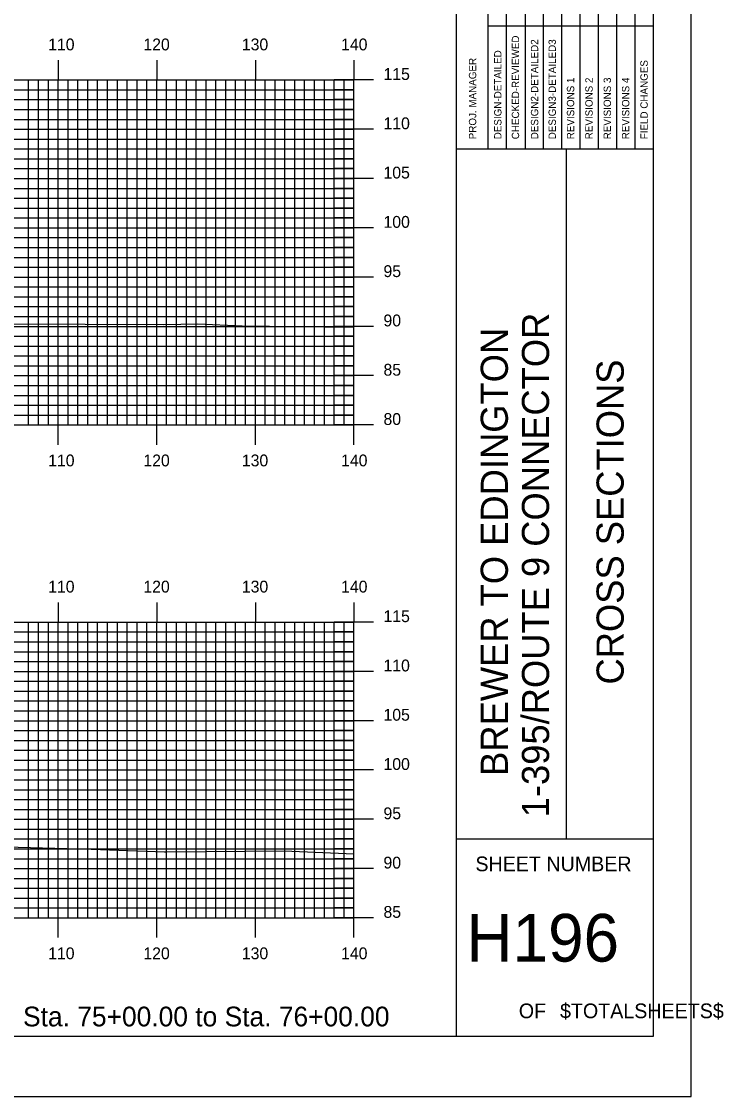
# Model space of a CAD drawing. Extents: x 1761397 to 1761741, y 442591 to 442811.
# Drawn here: x 1761669.5 to 1761740.7, y 442590.5 to 442699.6 of the extents above; entities that cross this region are included whole.
import ezdxf

# ---------------------------------------------------------------- set-up
doc = ezdxf.new("R2010")
doc.units = 0
for name, color, linetype in [('BORDER', 7, 'Continuous'), ('H_V ANNOTATION', 7, 'Continuous'), ('MAJOR', 7, 'Continuous'), ('MINOR', 7, 'Continuous'), ('PLOT BOUNDARY', 7, 'Continuous'), ('S_Roadway_Centerline', 7, 'Continuous')]:
    doc.layers.add(name, color=color, linetype=linetype)

msp = doc.modelspace()

# ---------------------------------------------------------------- linework, layer by layer
at = {"layer": 'BORDER'}
for p, q in [((1761713.64, 442596.67), (1761713.64, 442806.67)), ((1761713.64, 442686.67), (1761733.64, 442686.67)), ((1761724.82, 442616.67), (1761724.82, 442686.67)), ((1761713.64, 442616.67), (1761733.64, 442616.67))]:
    msp.add_line(p, q, dxfattribs=at)
msp.add_lwpolyline([(1761413.64, 442596.67), (1761733.64, 442596.67), (1761733.64, 442806.67), (1761413.64, 442806.67)], close=True, dxfattribs=at)
for points in [[(1761718.73, 442686.68), (1761718.73, 442721.67)], [(1761720.6, 442721.67), (1761720.6, 442686.68)], [(1761722.46, 442686.68), (1761722.46, 442721.67)], [(1761724.33, 442686.68), (1761724.33, 442721.67)], [(1761726.19, 442686.68), (1761726.19, 442721.67)], [(1761728.05, 442686.68), (1761728.05, 442721.67)], [(1761729.92, 442686.68), (1761729.92, 442721.67)], [(1761731.78, 442686.68), (1761731.78, 442721.67)], [(1761716.87, 442686.68), (1761716.87, 442720.26)], [(1761716.87, 442699.17), (1761733.64, 442699.17)]]:
    msp.add_lwpolyline(points, dxfattribs=at)
at = {"layer": 'MAJOR'}
for p, q in [((1761673.24, 442695.67), (1761673.24, 442693.67)), ((1761683.24, 442695.67), (1761683.24, 442693.67)), ((1761693.24, 442695.67), (1761693.24, 442693.67)), ((1761703.24, 442695.67), (1761703.24, 442693.67)), ((1761423.24, 442693.67), (1761703.24, 442693.67)), ((1761423.24, 442693.67), (1761703.24, 442693.67)), ((1761673.24, 442658.67), (1761673.24, 442693.67)), ((1761683.24, 442658.67), (1761683.24, 442693.67)), ((1761693.24, 442658.67), (1761693.24, 442693.67)), ((1761705.24, 442693.67), (1761701.24, 442693.67)), ((1761703.24, 442658.67), (1761703.24, 442693.67)), ((1761703.24, 442658.67), (1761703.24, 442693.67)), ((1761423.24, 442688.67), (1761703.24, 442688.67)), ((1761705.24, 442688.67), (1761701.24, 442688.67)), ((1761423.24, 442683.67), (1761703.24, 442683.67)), ((1761705.24, 442683.67), (1761701.24, 442683.67)), ((1761423.24, 442678.67), (1761703.24, 442678.67)), ((1761705.24, 442678.67), (1761701.24, 442678.67)), ((1761423.24, 442673.67), (1761703.24, 442673.67)), ((1761705.24, 442673.67), (1761701.24, 442673.67)), ((1761423.24, 442668.67), (1761703.24, 442668.67)), ((1761705.24, 442668.67), (1761701.24, 442668.67)), ((1761423.24, 442663.67), (1761703.24, 442663.67)), ((1761705.24, 442663.67), (1761701.24, 442663.67)), ((1761423.24, 442658.67), (1761703.24, 442658.67)), ((1761423.24, 442658.67), (1761703.24, 442658.67)), ((1761673.24, 442656.66), (1761673.24, 442658.67)), ((1761683.24, 442656.66), (1761683.24, 442658.67)), ((1761693.24, 442656.66), (1761693.24, 442658.67)), ((1761705.24, 442658.67), (1761701.24, 442658.67)), ((1761703.24, 442656.66), (1761703.24, 442658.67)), ((1761673.24, 442640.67), (1761673.24, 442638.67)), ((1761683.24, 442640.67), (1761683.24, 442638.67)), ((1761693.24, 442640.67), (1761693.24, 442638.67)), ((1761703.24, 442640.67), (1761703.24, 442638.67)), ((1761423.24, 442638.67), (1761703.24, 442638.67)), ((1761423.24, 442638.67), (1761703.24, 442638.67)), ((1761673.24, 442608.67), (1761673.24, 442638.67)), ((1761683.24, 442608.67), (1761683.24, 442638.67)), ((1761693.24, 442608.67), (1761693.24, 442638.67)), ((1761705.24, 442638.67), (1761701.24, 442638.67)), ((1761703.24, 442608.67), (1761703.24, 442638.67)), ((1761703.24, 442608.67), (1761703.24, 442638.67)), ((1761423.24, 442633.67), (1761703.24, 442633.67)), ((1761705.24, 442633.67), (1761701.24, 442633.67)), ((1761423.24, 442628.67), (1761703.24, 442628.67)), ((1761705.24, 442628.67), (1761701.24, 442628.67)), ((1761423.24, 442623.67), (1761703.24, 442623.67)), ((1761705.24, 442623.67), (1761701.24, 442623.67)), ((1761423.24, 442618.67), (1761703.24, 442618.67)), ((1761705.24, 442618.67), (1761701.24, 442618.67)), ((1761423.24, 442613.67), (1761703.24, 442613.67)), ((1761705.24, 442613.67), (1761701.24, 442613.67)), ((1761423.24, 442608.67), (1761703.24, 442608.67)), ((1761423.24, 442608.67), (1761703.24, 442608.67)), ((1761673.24, 442606.66), (1761673.24, 442608.67)), ((1761683.24, 442606.66), (1761683.24, 442608.67)), ((1761693.24, 442606.66), (1761693.24, 442608.67)), ((1761705.24, 442608.67), (1761701.24, 442608.67)), ((1761703.24, 442606.66), (1761703.24, 442608.67))]:
    msp.add_line(p, q, dxfattribs=at)
at = {"layer": 'MINOR'}
for p, q in [((1761670.24, 442658.67), (1761670.24, 442693.67)), ((1761671.24, 442658.67), (1761671.24, 442693.67)), ((1761672.24, 442658.67), (1761672.24, 442693.67)), ((1761674.24, 442658.67), (1761674.24, 442693.67)), ((1761675.24, 442658.67), (1761675.24, 442693.67)), ((1761676.24, 442658.67), (1761676.24, 442693.67)), ((1761677.24, 442658.67), (1761677.24, 442693.67)), ((1761678.24, 442658.67), (1761678.24, 442693.67)), ((1761679.24, 442658.67), (1761679.24, 442693.67)), ((1761680.24, 442658.67), (1761680.24, 442693.67)), ((1761681.24, 442658.67), (1761681.24, 442693.67)), ((1761682.24, 442658.67), (1761682.24, 442693.67)), ((1761684.24, 442658.67), (1761684.24, 442693.67)), ((1761685.24, 442658.67), (1761685.24, 442693.67)), ((1761686.24, 442658.67), (1761686.24, 442693.67)), ((1761687.24, 442658.67), (1761687.24, 442693.67)), ((1761688.24, 442658.67), (1761688.24, 442693.67)), ((1761689.24, 442658.67), (1761689.24, 442693.67)), ((1761690.24, 442658.67), (1761690.24, 442693.67)), ((1761691.24, 442658.67), (1761691.24, 442693.67)), ((1761692.24, 442658.67), (1761692.24, 442693.67)), ((1761694.24, 442658.67), (1761694.24, 442693.67)), ((1761695.24, 442658.67), (1761695.24, 442693.67)), ((1761696.24, 442658.67), (1761696.24, 442693.67)), ((1761697.24, 442658.67), (1761697.24, 442693.67)), ((1761698.24, 442658.67), (1761698.24, 442693.67)), ((1761699.24, 442658.67), (1761699.24, 442693.67)), ((1761700.24, 442658.67), (1761700.24, 442693.67)), ((1761701.24, 442658.67), (1761701.24, 442693.67)), ((1761702.24, 442658.67), (1761702.24, 442693.67)), ((1761423.24, 442692.67), (1761703.24, 442692.67)), ((1761423.24, 442691.67), (1761703.24, 442691.67)), ((1761703.24, 442692.67), (1761701.24, 442692.67)), ((1761703.24, 442691.67), (1761701.24, 442691.67)), ((1761423.24, 442690.67), (1761703.24, 442690.67)), ((1761703.24, 442690.67), (1761701.24, 442690.67)), ((1761423.24, 442689.67), (1761703.24, 442689.67)), ((1761703.24, 442689.67), (1761701.24, 442689.67)), ((1761423.24, 442687.67), (1761703.24, 442687.67)), ((1761703.24, 442687.67), (1761701.24, 442687.67)), ((1761423.24, 442686.67), (1761703.24, 442686.67)), ((1761703.24, 442686.67), (1761701.24, 442686.67)), ((1761423.24, 442685.67), (1761703.24, 442685.67)), ((1761703.24, 442685.67), (1761701.24, 442685.67)), ((1761423.24, 442684.67), (1761703.24, 442684.67)), ((1761703.24, 442684.67), (1761701.24, 442684.67)), ((1761423.24, 442682.67), (1761703.24, 442682.67)), ((1761703.24, 442682.67), (1761701.24, 442682.67)), ((1761423.24, 442681.67), (1761703.24, 442681.67)), ((1761703.24, 442681.67), (1761701.24, 442681.67)), ((1761423.24, 442680.67), (1761703.24, 442680.67)), ((1761423.24, 442679.67), (1761703.24, 442679.67)), ((1761703.24, 442680.67), (1761701.24, 442680.67)), ((1761703.24, 442679.67), (1761701.24, 442679.67)), ((1761423.24, 442677.67), (1761703.24, 442677.67)), ((1761703.24, 442677.67), (1761701.24, 442677.67)), ((1761423.24, 442676.67), (1761703.24, 442676.67)), ((1761703.24, 442676.67), (1761701.24, 442676.67)), ((1761423.24, 442675.67), (1761703.24, 442675.67)), ((1761703.24, 442675.67), (1761701.24, 442675.67)), ((1761423.24, 442674.67), (1761703.24, 442674.67)), ((1761703.24, 442674.67), (1761701.24, 442674.67)), ((1761423.24, 442672.67), (1761703.24, 442672.67)), ((1761703.24, 442672.67), (1761701.24, 442672.67)), ((1761423.24, 442671.67), (1761703.24, 442671.67)), ((1761703.24, 442671.67), (1761701.24, 442671.67)), ((1761423.24, 442670.67), (1761703.24, 442670.67)), ((1761703.24, 442670.67), (1761701.24, 442670.67)), ((1761423.24, 442669.67), (1761703.24, 442669.67)), ((1761703.24, 442669.67), (1761701.24, 442669.67)), ((1761423.24, 442667.67), (1761703.24, 442667.67)), ((1761703.24, 442667.67), (1761701.24, 442667.67)), ((1761423.24, 442666.67), (1761703.24, 442666.67)), ((1761703.24, 442666.67), (1761701.24, 442666.67)), ((1761423.24, 442665.67), (1761703.24, 442665.67)), ((1761703.24, 442665.67), (1761701.24, 442665.67)), ((1761423.24, 442664.67), (1761703.24, 442664.67)), ((1761703.24, 442664.67), (1761701.24, 442664.67)), ((1761423.24, 442662.67), (1761703.24, 442662.67)), ((1761703.24, 442662.67), (1761701.24, 442662.67)), ((1761423.24, 442661.67), (1761703.24, 442661.67)), ((1761703.24, 442661.67), (1761701.24, 442661.67)), ((1761423.24, 442660.67), (1761703.24, 442660.67)), ((1761703.24, 442660.67), (1761701.24, 442660.67)), ((1761423.24, 442659.67), (1761703.24, 442659.67)), ((1761703.24, 442659.67), (1761701.24, 442659.67)), ((1761670.24, 442608.67), (1761670.24, 442638.67)), ((1761671.24, 442608.67), (1761671.24, 442638.67)), ((1761672.24, 442608.67), (1761672.24, 442638.67)), ((1761674.24, 442608.67), (1761674.24, 442638.67)), ((1761675.24, 442608.67), (1761675.24, 442638.67)), ((1761676.24, 442608.67), (1761676.24, 442638.67)), ((1761677.24, 442608.67), (1761677.24, 442638.67)), ((1761678.24, 442608.67), (1761678.24, 442638.67)), ((1761679.24, 442608.67), (1761679.24, 442638.67)), ((1761680.24, 442608.67), (1761680.24, 442638.67)), ((1761681.24, 442608.67), (1761681.24, 442638.67)), ((1761682.24, 442608.67), (1761682.24, 442638.67)), ((1761684.24, 442608.67), (1761684.24, 442638.67)), ((1761685.24, 442608.67), (1761685.24, 442638.67)), ((1761686.24, 442608.67), (1761686.24, 442638.67)), ((1761687.24, 442608.67), (1761687.24, 442638.67)), ((1761688.24, 442608.67), (1761688.24, 442638.67)), ((1761689.24, 442608.67), (1761689.24, 442638.67)), ((1761690.24, 442608.67), (1761690.24, 442638.67)), ((1761691.24, 442608.67), (1761691.24, 442638.67)), ((1761692.24, 442608.67), (1761692.24, 442638.67)), ((1761694.24, 442608.67), (1761694.24, 442638.67)), ((1761695.24, 442608.67), (1761695.24, 442638.67)), ((1761696.24, 442608.67), (1761696.24, 442638.67)), ((1761697.24, 442608.67), (1761697.24, 442638.67)), ((1761698.24, 442608.67), (1761698.24, 442638.67)), ((1761699.24, 442608.67), (1761699.24, 442638.67)), ((1761700.24, 442608.67), (1761700.24, 442638.67)), ((1761701.24, 442608.67), (1761701.24, 442638.67)), ((1761702.24, 442608.67), (1761702.24, 442638.67)), ((1761423.24, 442637.67), (1761703.24, 442637.67)), ((1761703.24, 442637.67), (1761701.24, 442637.67)), ((1761423.24, 442636.67), (1761703.24, 442636.67)), ((1761703.24, 442636.67), (1761701.24, 442636.67)), ((1761423.24, 442635.67), (1761703.24, 442635.67)), ((1761703.24, 442635.67), (1761701.24, 442635.67)), ((1761423.24, 442634.67), (1761703.24, 442634.67)), ((1761703.24, 442634.67), (1761701.24, 442634.67)), ((1761423.24, 442632.67), (1761703.24, 442632.67)), ((1761703.24, 442632.67), (1761701.24, 442632.67)), ((1761423.24, 442631.67), (1761703.24, 442631.67)), ((1761423.24, 442630.67), (1761703.24, 442630.67)), ((1761703.24, 442631.67), (1761701.24, 442631.67)), ((1761703.24, 442630.67), (1761701.24, 442630.67)), ((1761423.24, 442629.67), (1761703.24, 442629.67)), ((1761703.24, 442629.67), (1761701.24, 442629.67)), ((1761423.24, 442627.67), (1761703.24, 442627.67)), ((1761703.24, 442627.67), (1761701.24, 442627.67)), ((1761423.24, 442626.67), (1761703.24, 442626.67)), ((1761703.24, 442626.67), (1761701.24, 442626.67)), ((1761423.24, 442625.67), (1761703.24, 442625.67)), ((1761703.24, 442625.67), (1761701.24, 442625.67)), ((1761423.24, 442624.67), (1761703.24, 442624.67)), ((1761703.24, 442624.67), (1761701.24, 442624.67)), ((1761423.24, 442622.67), (1761703.24, 442622.67)), ((1761703.24, 442622.67), (1761701.24, 442622.67)), ((1761423.24, 442621.67), (1761703.24, 442621.67)), ((1761703.24, 442621.67), (1761701.24, 442621.67)), ((1761423.24, 442620.67), (1761703.24, 442620.67)), ((1761703.24, 442620.67), (1761701.24, 442620.67)), ((1761423.24, 442619.67), (1761703.24, 442619.67)), ((1761703.24, 442619.67), (1761701.24, 442619.67)), ((1761423.24, 442617.67), (1761703.24, 442617.67)), ((1761703.24, 442617.67), (1761701.24, 442617.67)), ((1761423.24, 442616.67), (1761703.24, 442616.67)), ((1761703.24, 442616.67), (1761701.24, 442616.67)), ((1761423.24, 442615.67), (1761703.24, 442615.67)), ((1761703.24, 442615.67), (1761701.24, 442615.67)), ((1761423.24, 442614.67), (1761703.24, 442614.67)), ((1761703.24, 442614.67), (1761701.24, 442614.67)), ((1761423.24, 442612.67), (1761703.24, 442612.67)), ((1761703.24, 442612.67), (1761701.24, 442612.67)), ((1761423.24, 442611.67), (1761703.24, 442611.67)), ((1761703.24, 442611.67), (1761701.24, 442611.67)), ((1761423.24, 442610.67), (1761703.24, 442610.67)), ((1761703.24, 442610.67), (1761701.24, 442610.67)), ((1761423.24, 442609.67), (1761703.24, 442609.67)), ((1761703.24, 442609.67), (1761701.24, 442609.67))]:
    msp.add_line(p, q, dxfattribs=at)
at = {"layer": 'PLOT BOUNDARY'}
msp.add_lwpolyline([(1761397.45, 442590.55), (1761737.45, 442590.55), (1761737.45, 442810.55), (1761397.45, 442810.55)], close=True, dxfattribs=at)
at = {"layer": 'S_Roadway_Centerline'}
for points in [[(1761621.05, 442669.82), (1761632.88, 442669.81), (1761632.96, 442669.81), (1761642.33, 442669.39), (1761642.44, 442669.39), (1761653.87, 442669.16), (1761663.01, 442668.95), (1761665.23, 442668.91), (1761668, 442668.92), (1761683.96, 442668.86), (1761687.42, 442668.92), (1761691.89, 442668.73), (1761700.2, 442668.64), (1761703.24, 442668.6)], [(1761617.39, 442616.34), (1761622.81, 442616.06), (1761633.63, 442615.69), (1761646.9, 442616.37), (1761649.84, 442616.72), (1761654.63, 442617.01), (1761656, 442616.69), (1761662.99, 442616), (1761674.1, 442615.71), (1761675.03, 442615.66), (1761675.67, 442615.66), (1761684.03, 442615.36), (1761684.21, 442615.36), (1761696.16, 442615.48), (1761703.24, 442615.18)]]:
    msp.add_lwpolyline(points, dxfattribs=at)

# ---------------------------------------------------------------- texts
at = {"layer": 'BORDER'}
for s, height, p in [('CHECKED-REVIEWED', 0.7455, (1761720, 442687.65)), ('DESIGN2-DETAILED2', 0.7455, (1761721.94, 442687.65)), ('DESIGN3-DETAILED3', 0.7455, (1761723.73, 442687.65)), ('DESIGN-DETAILED', 0.7455, (1761718.21, 442687.65)), ('PROJ. MANAGER', 0.7455, (1761715.65, 442687.65)), ('FIELD CHANGES', 0.7455, (1761733.05, 442687.65)), ('REVISIONS 1', 0.7455, (1761725.59, 442687.65)), ('REVISIONS 2', 0.7455, (1761727.46, 442687.65)), ('REVISIONS 3', 0.7455, (1761729.32, 442687.65)), ('REVISIONS 4', 0.7455, (1761731.18, 442687.65)), ('1-395/ROUTE 9 CONNECTOR', 2.7557, (1761723.04, 442618.87)), ('BREWER TO EDDINGTON', 2.7557, (1761718.86, 442623.07)), ('CROSS SECTIONS', 2.7557, (1761730.61, 442632.34))]:
    msp.add_text(s, height=height, rotation=90, dxfattribs=at).set_placement(p)
for s, height, p in [('SHEET NUMBER', 1.4905, (1761715.57, 442613.4)), ('H196', 4.839, (1761714.67, 442604.23)), ('$TOTALSHEETS$', 1.4905, (1761724.15, 442598.49)), ('OF', 1.491, (1761719.97, 442598.49))]:
    msp.add_text(s, height=height, dxfattribs=at).set_placement(p)
at = {"layer": 'H_V ANNOTATION'}
for s, height, p in [('110', 1.2, (1761672.22, 442696.67)), ('120', 1.2, (1761681.88, 442696.67)), ('130', 1.2, (1761691.87, 442696.67)), ('140', 1.2, (1761701.94, 442696.67)), ('115', 1.2, (1761706.24, 442693.67)), ('110', 1.2, (1761706.24, 442688.67)), ('105', 1.2, (1761706.24, 442683.67)), ('100', 1.2, (1761706.24, 442678.67)), ('95', 1.2, (1761706.24, 442673.67)), ('90', 1.2, (1761706.24, 442668.67)), ('85', 1.2, (1761706.24, 442663.67)), ('80', 1.2, (1761706.24, 442658.67)), ('110', 1.2, (1761672.22, 442654.47)), ('120', 1.2, (1761681.88, 442654.47)), ('130', 1.2, (1761691.87, 442654.47)), ('140', 1.2, (1761701.94, 442654.47)), ('110', 1.2, (1761672.22, 442641.67)), ('120', 1.2, (1761681.88, 442641.67)), ('130', 1.2, (1761691.87, 442641.67)), ('140', 1.2, (1761701.94, 442641.67)), ('115', 1.2, (1761706.24, 442638.67)), ('110', 1.2, (1761706.24, 442633.67)), ('105', 1.2, (1761706.24, 442628.67)), ('100', 1.2, (1761706.24, 442623.67)), ('95', 1.2, (1761706.24, 442618.67)), ('90', 1.2, (1761706.24, 442613.67)), ('85', 1.2, (1761706.24, 442608.67)), ('110', 1.2, (1761672.22, 442604.47)), ('120', 1.2, (1761681.88, 442604.47)), ('130', 1.2, (1761691.87, 442604.47)), ('140', 1.2, (1761701.94, 442604.47)), ('Sta. 75+00.00 to Sta. 76+00.00', 2.0004, (1761669.67, 442597.66))]:
    msp.add_text(s, height=height, dxfattribs=at).set_placement(p)

doc.saveas('drawing.dxf')
